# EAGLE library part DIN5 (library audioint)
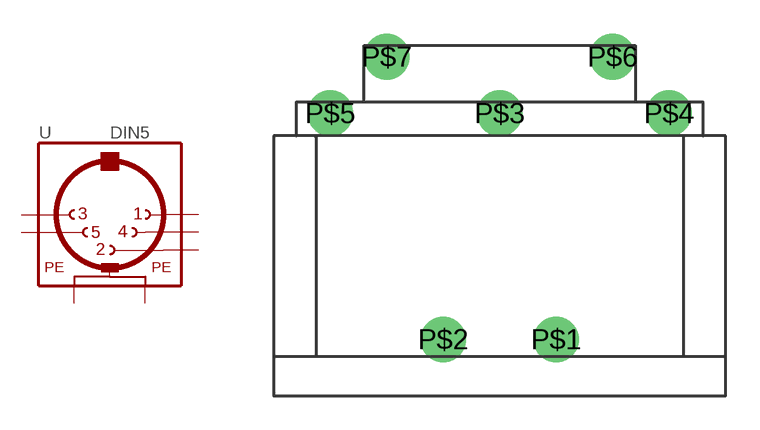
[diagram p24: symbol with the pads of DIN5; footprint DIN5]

Designator prefix -

## DIN5CUI/SDS-50J  [DIN5]
P$1  PE  pwr
P$2  PE  pwr
P$3  2  pas
P$4  1  pas
P$5  3  pas
P$6  4  pas
P$7  5  pas

## Footprint DIN5 (pad centres in mm)
drill 1.346 round: P$1 2.5,2.5; P$2 -2.5,2.5; P$3 0,12.5; P$4 7.5,12.5; P$5 -7.5,12.5; P$6 5,15; P$7 -5,15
